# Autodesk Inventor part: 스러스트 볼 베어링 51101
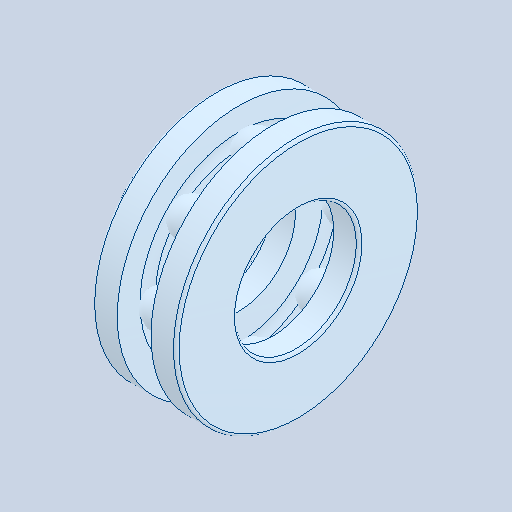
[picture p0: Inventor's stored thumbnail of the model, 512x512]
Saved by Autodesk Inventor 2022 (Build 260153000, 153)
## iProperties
Created: 2024-07
Part Number: 스러스트 볼 베어링 51101
Material: 강철, 연강
Description: 롤링 베어링 - 플랫 뒷면이 있는 스러스트 볼 베어링
Document SubType Name: Modeling
Designer: PC-01
Density: 7.85 g/cm^3
Appearance: 기본값
Author: jhkim
Sending System: Autodesk Inventor 2025
Preprocessor: ST-DEVELOPER v20
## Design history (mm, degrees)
feature "Solid1"
feature "Solid1:1"
feature "Solid1:2"
feature "Solid1:3"
feature "Solid1:4"
feature "Solid1:5"
feature "Solid1:6"
feature "Solid1:7"
feature "Solid1:8"
feature "Solid1:9"
node "솔리드1"
node "솔리드2"
node "솔리드3"
node "솔리드4"
node "솔리드5"
node "솔리드6"
node "솔리드7"
node "솔리드8"
node "솔리드9"
node "솔리드10"
